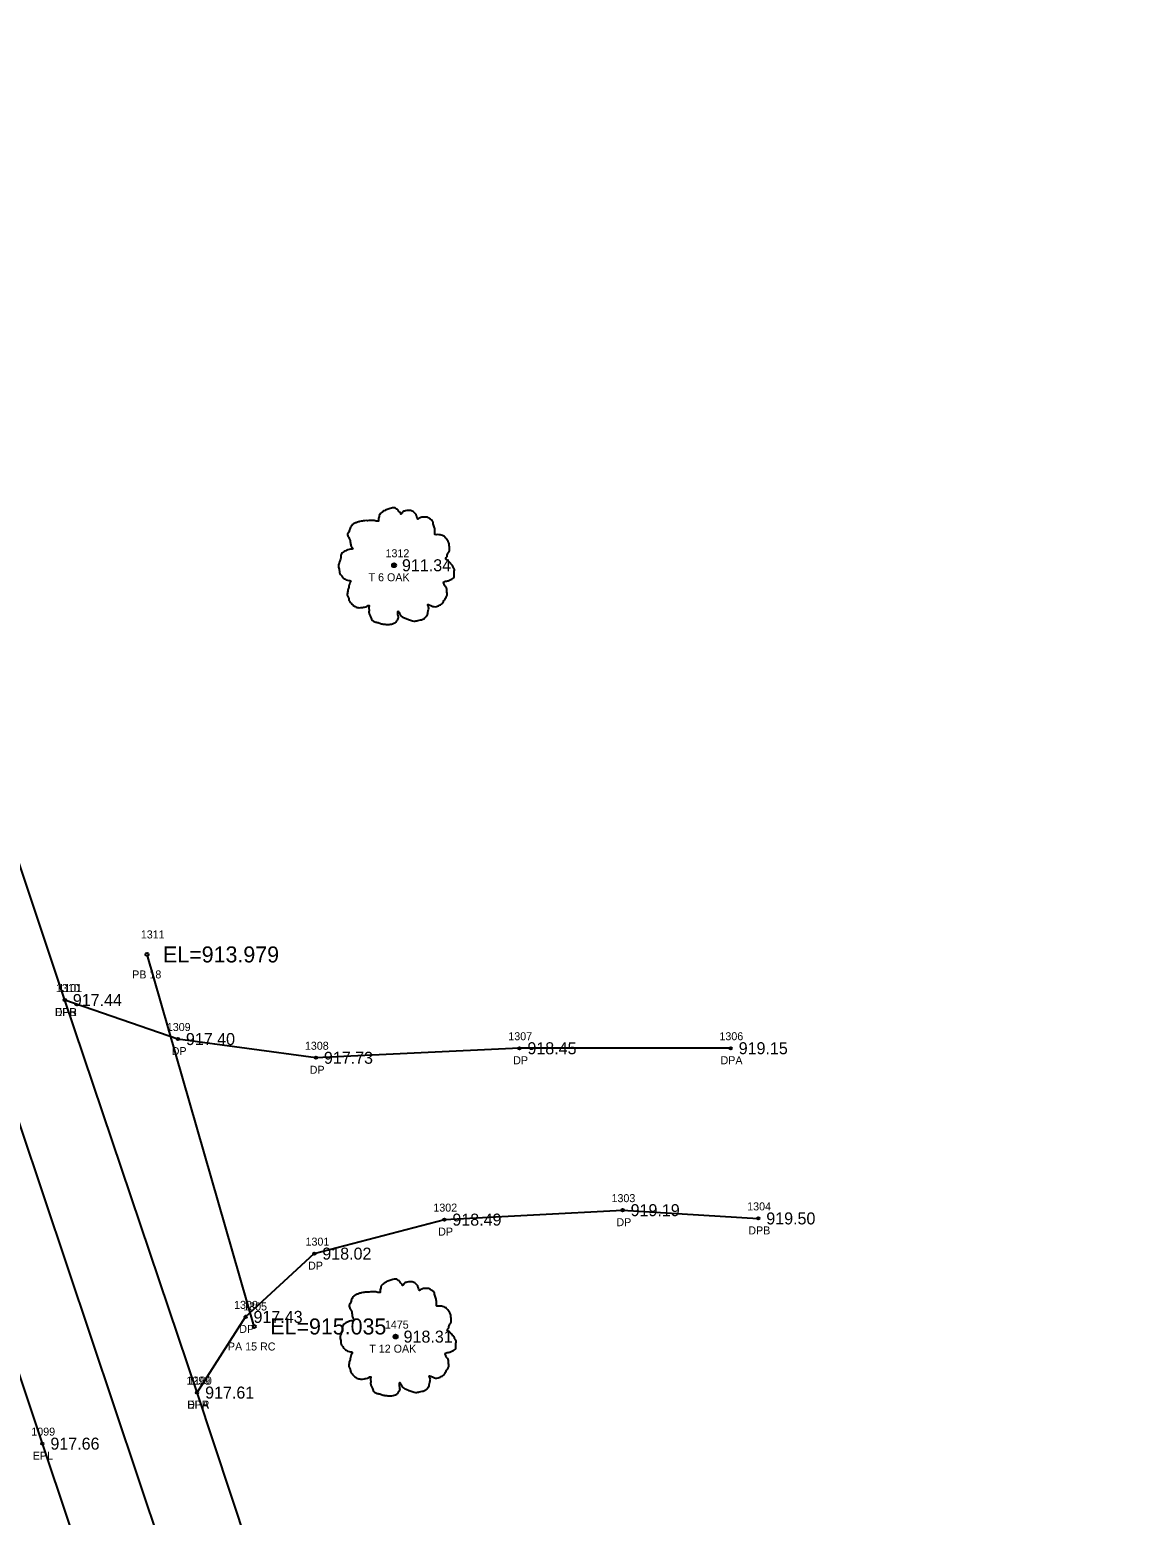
# Model space of a CAD drawing. Extents: x 1528109 to 1531398, y 1157799 to 1162548.
# Drawn here: x 1529835.3 to 1529973.9, y 1159675.3 to 1159860.9 of the extents above; entities that cross this region are included whole.
import ezdxf

# ---------------------------------------------------------------- set-up
doc = ezdxf.new("R2010")
doc.units = 0
for name, color, linetype in [('RD_EX_DR_Pipe', 7, 'Continuous'), ('RD_EX_DR_Pipe_txCode', 7, 'Continuous'), ('RD_EX_Driveway', 7, 'Continuous'), ('RD_EX_Driveway_txCode', 7, 'Continuous'), ('RD_EX_Road', 7, 'Continuous'), ('RD_EX_Road_txCode', 7, 'Continuous'), ('RD_EX_TX_Driveway_ELEV', 7, 'Continuous'), ('RD_EX_TX_Road_ELEV', 7, 'Continuous'), ('RD_EX_TX_VEG_ELEV', 7, 'Continuous'), ('RD_EX_VEG', 7, 'Continuous'), ('RD_EX_VEG_txCode', 7, 'Continuous'), ('RD_HC_Cl', 7, 'Continuous'), ('RD_SMD_Locator', 7, 'Continuous'), ('RD_TX_Pipe_ElevEX', 7, 'Continuous')]:
    doc.layers.add(name, color=color, linetype=linetype)

msp = doc.modelspace()

# ---------------------------------------------------------------- linework, layer by layer
at = {"layer": 'RD_EX_DR_Pipe'}
msp.add_line((1529863.43, 1159698.93), (1529850.02, 1159745.41), dxfattribs=at)
at = {"layer": 'RD_EX_Driveway'}
for points in [[(1529922.98, 1159733.69), (1529896.57, 1159733.69), (1529871.13, 1159732.5), (1529853.88, 1159734.84), (1529839.74, 1159739.71)], [(1529856.28, 1159690.67), (1529862.33, 1159700.13), (1529870.93, 1159708.03), (1529887.19, 1159712.28), (1529909.47, 1159713.46), (1529926.43, 1159712.43)]]:
    msp.add_lwpolyline(points, dxfattribs=at)
at = {"layer": 'RD_EX_Road'}
for points in [[(1530337.52, 1159156.44), (1530294.13, 1159166.93), (1530250.93, 1159177.7), (1530204.42, 1159191.5), (1530168.45, 1159204.97), (1530120.58, 1159231.54), (1530104.56, 1159243.15), (1530086.77, 1159257.61), (1530051.98, 1159290.88), (1530019.2, 1159326.18), (1529978.15, 1159378.31), (1529959.68, 1159408.2), (1529942.81, 1159442.34), (1529934.79, 1159460.88), (1529923.22, 1159491.09), (1529910.46, 1159527.95), (1529895.99, 1159570.93), (1529881.69, 1159613.98), (1529856.28, 1159690.67), (1529839.74, 1159739.71), (1529819.57, 1159800.04), (1529788.95, 1159890.99)], [(1530332.28, 1159136.67), (1530288.96, 1159147.06), (1530245.68, 1159158), (1530197.52, 1159172.18), (1530159.1, 1159186.57), (1530108.6, 1159214.89), (1530072.67, 1159242.37), (1530037.12, 1159276.96), (1530005.21, 1159311.5), (1529961.59, 1159366.88), (1529941.79, 1159398.29), (1529924.06, 1159434.11), (1529903.77, 1159484.39), (1529891.44, 1159520.8), (1529876.79, 1159564.7), (1529862.9, 1159606.82), (1529836.94, 1159684.29), (1529820.66, 1159733.09), (1529800.02, 1159794.4), (1529769.54, 1159884.46)]]:
    msp.add_lwpolyline(points, dxfattribs=at)
at = {"layer": 'RD_EX_VEG'}
for centre, radius in [((1529880.89, 1159794.03), 0.25), ((1529880.88, 1159794.01), 0.0001), ((1529881.09, 1159697.66), 0.25), ((1529881.08, 1159697.64), 0.0001)]:
    msp.add_circle(centre, radius, dxfattribs=at)
for points in [[(1529881.02, 1159801.2), (1529880.72, 1159801.22), (1529880.4, 1159801.12), (1529880.15, 1159801.02), (1529879.92, 1159800.95), (1529879.7, 1159800.85), (1529879.4, 1159800.68), (1529879.17, 1159800.48), (1529879.05, 1159800.23), (1529879, 1159800), (1529878.95, 1159799.73), (1529878.95, 1159799.55), (1529878.82, 1159799.53), (1529878.67, 1159799.55), (1529878.42, 1159799.63), (1529878.17, 1159799.63), (1529877.92, 1159799.63), (1529877.57, 1159799.6), (1529877.22, 1159799.6), (1529876.95, 1159799.55), (1529876.62, 1159799.5), (1529876.25, 1159799.38), (1529875.9, 1159799.25), (1529875.6, 1159799), (1529875.35, 1159798.53), (1529875.23, 1159798.18), (1529875.08, 1159797.93), (1529875.23, 1159797.48), (1529875.4, 1159797.13), (1529875.43, 1159796.93), (1529875.5, 1159796.5), (1529875.6, 1159796.28), (1529875.73, 1159796.08), (1529875.65, 1159796.05), (1529875.28, 1159796), (1529874.98, 1159795.9), (1529874.55, 1159795.68), (1529874.33, 1159795.45), (1529874.23, 1159795.13), (1529874.2, 1159794.78), (1529874.1, 1159794.58), (1529874.03, 1159794.3), (1529874, 1159794.23), (1529873.95, 1159793.9), (1529874.05, 1159793.45), (1529874.08, 1159793.1), (1529874.2, 1159792.88), (1529874.35, 1159792.7), (1529874.53, 1159792.45), (1529874.93, 1159792.23), (1529875.25, 1159792.13), (1529875.45, 1159792.1), (1529875.28, 1159791.6), (1529875.23, 1159791.25), (1529875.1, 1159790.85), (1529875.1, 1159790.78), (1529875.05, 1159790.3), (1529875.2, 1159789.98), (1529875.28, 1159789.6), (1529875.45, 1159789.38), (1529875.73, 1159789.08), (1529876.05, 1159788.86), (1529876.55, 1159788.73), (1529876.95, 1159788.76), (1529877.52, 1159788.93), (1529877.77, 1159789.01), (1529877.75, 1159788.83), (1529877.77, 1159788.46), (1529877.77, 1159788.03), (1529877.92, 1159787.71), (1529878.02, 1159787.43), (1529878.17, 1159787.18), (1529878.5, 1159786.96), (1529878.9, 1159786.88), (1529879.32, 1159786.73), (1529879.77, 1159786.66), (1529880.27, 1159786.63), (1529880.87, 1159786.78), (1529881.15, 1159786.91), (1529881.25, 1159787.08), (1529881.45, 1159787.46), (1529881.4, 1159787.68), (1529881.42, 1159788.28), (1529881.52, 1159788.11), (1529881.7, 1159787.76), (1529882.2, 1159787.46), (1529882.6, 1159787.28), (1529883.07, 1159787.13), (1529883.37, 1159787.06), (1529883.85, 1159787.13), (1529884.22, 1159787.21), (1529884.6, 1159787.33), (1529884.9, 1159787.61), (1529885.07, 1159787.88), (1529885.12, 1159788.16), (1529885.2, 1159788.53), (1529885.25, 1159788.71)], [(1529885.25, 1159788.71), (1529885.17, 1159788.88), (1529885.12, 1159789.13), (1529885.2, 1159789.11), (1529885.37, 1159789.06), (1529885.65, 1159788.93), (1529885.87, 1159788.86), (1529886.2, 1159788.88), (1529886.47, 1159788.98), (1529886.92, 1159789.26), (1529887.2, 1159789.73), (1529887.47, 1159790.13), (1529887.54, 1159790.45), (1529887.49, 1159790.68), (1529887.47, 1159791.18), (1529887.27, 1159791.43), (1529887.22, 1159791.55), (1529887.12, 1159791.95), (1529887.2, 1159792), (1529887.47, 1159792.05), (1529887.84, 1159792.18), (1529888.12, 1159792.3), (1529888.34, 1159792.48), (1529888.42, 1159792.7), (1529888.39, 1159793.1), (1529888.44, 1159793.5), (1529888.37, 1159793.65), (1529888.27, 1159793.8), (1529888.19, 1159794), (1529888.04, 1159794.15), (1529887.94, 1159794.3), (1529887.84, 1159794.4), (1529887.72, 1159794.55), (1529887.54, 1159794.68), (1529887.4, 1159794.73), (1529887.35, 1159794.88), (1529887.49, 1159795.08), (1529887.54, 1159795.18), (1529887.57, 1159795.4), (1529887.79, 1159795.75), (1529887.84, 1159796.15), (1529887.79, 1159796.58), (1529887.74, 1159796.85), (1529887.59, 1159797.13), (1529887.4, 1159797.38), (1529887.27, 1159797.55), (1529887.1, 1159797.68), (1529886.77, 1159797.8), (1529886.52, 1159797.85), (1529886.17, 1159797.85), (1529885.97, 1159797.9), (1529886, 1159797.95), (1529886, 1159798.1), (1529886, 1159798.38), (1529885.92, 1159798.83), (1529885.77, 1159799.33), (1529885.77, 1159799.35), (1529885.67, 1159799.6), (1529885.45, 1159799.8), (1529885.27, 1159799.9), (1529885.07, 1159800.03), (1529884.82, 1159800.05), (1529884.52, 1159800.05), (1529884.25, 1159800), (1529884.05, 1159799.9), (1529883.87, 1159799.78), (1529883.8, 1159799.93), (1529883.7, 1159800.23), (1529883.65, 1159800.38), (1529883.5, 1159800.55), (1529883.27, 1159800.75), (1529882.82, 1159800.87), (1529882.2, 1159800.8), (1529881.9, 1159800.6), (1529881.75, 1159800.43), (1529881.7, 1159800.55), (1529881.5, 1159800.75), (1529881.4, 1159800.92), (1529881.22, 1159801.05), (1529881.07, 1159801.15), (1529880.97, 1159801.2)], [(1529881.23, 1159704.83), (1529880.93, 1159704.85), (1529880.6, 1159704.75), (1529880.35, 1159704.66), (1529880.13, 1159704.58), (1529879.9, 1159704.48), (1529879.6, 1159704.31), (1529879.38, 1159704.11), (1529879.25, 1159703.86), (1529879.2, 1159703.63), (1529879.15, 1159703.36), (1529879.15, 1159703.18), (1529879.03, 1159703.16), (1529878.88, 1159703.18), (1529878.63, 1159703.26), (1529878.38, 1159703.26), (1529878.13, 1159703.26), (1529877.78, 1159703.23), (1529877.43, 1159703.23), (1529877.15, 1159703.18), (1529876.83, 1159703.13), (1529876.45, 1159703.01), (1529876.1, 1159702.88), (1529875.8, 1159702.63), (1529875.55, 1159702.16), (1529875.43, 1159701.81), (1529875.28, 1159701.56), (1529875.43, 1159701.11), (1529875.6, 1159700.76), (1529875.63, 1159700.56), (1529875.7, 1159700.13), (1529875.8, 1159699.91), (1529875.93, 1159699.71), (1529875.85, 1159699.68), (1529875.48, 1159699.63), (1529875.18, 1159699.53), (1529874.75, 1159699.31), (1529874.53, 1159699.08), (1529874.43, 1159698.76), (1529874.4, 1159698.41), (1529874.3, 1159698.21), (1529874.23, 1159697.93), (1529874.2, 1159697.86), (1529874.15, 1159697.53), (1529874.25, 1159697.08), (1529874.28, 1159696.73), (1529874.4, 1159696.51), (1529874.55, 1159696.33), (1529874.73, 1159696.08), (1529875.13, 1159695.86), (1529875.45, 1159695.76), (1529875.65, 1159695.73), (1529875.48, 1159695.23), (1529875.43, 1159694.88), (1529875.3, 1159694.48), (1529875.3, 1159694.41), (1529875.25, 1159693.93), (1529875.4, 1159693.61), (1529875.48, 1159693.24), (1529875.65, 1159693.01), (1529875.93, 1159692.71), (1529876.25, 1159692.49), (1529876.75, 1159692.36), (1529877.15, 1159692.39), (1529877.73, 1159692.56), (1529877.98, 1159692.64), (1529877.95, 1159692.46), (1529877.98, 1159692.09), (1529877.98, 1159691.66), (1529878.13, 1159691.34), (1529878.23, 1159691.06), (1529878.38, 1159690.81), (1529878.7, 1159690.59), (1529879.1, 1159690.51), (1529879.53, 1159690.36), (1529879.98, 1159690.29), (1529880.48, 1159690.26), (1529881.08, 1159690.41), (1529881.35, 1159690.54), (1529881.45, 1159690.71), (1529881.65, 1159691.09), (1529881.6, 1159691.31), (1529881.63, 1159691.91), (1529881.73, 1159691.74), (1529881.9, 1159691.39), (1529882.4, 1159691.09), (1529882.8, 1159690.91), (1529883.28, 1159690.76), (1529883.58, 1159690.69), (1529884.05, 1159690.76), (1529884.42, 1159690.84), (1529884.8, 1159690.96), (1529885.1, 1159691.24), (1529885.27, 1159691.51), (1529885.32, 1159691.79), (1529885.4, 1159692.16), (1529885.45, 1159692.34)], [(1529885.45, 1159692.34), (1529885.37, 1159692.51), (1529885.32, 1159692.76), (1529885.4, 1159692.74), (1529885.57, 1159692.69), (1529885.85, 1159692.56), (1529886.07, 1159692.49), (1529886.4, 1159692.51), (1529886.67, 1159692.61), (1529887.12, 1159692.89), (1529887.4, 1159693.36), (1529887.67, 1159693.76), (1529887.75, 1159694.08), (1529887.7, 1159694.31), (1529887.67, 1159694.81), (1529887.47, 1159695.06), (1529887.42, 1159695.18), (1529887.32, 1159695.58), (1529887.4, 1159695.63), (1529887.67, 1159695.68), (1529888.05, 1159695.81), (1529888.32, 1159695.93), (1529888.55, 1159696.11), (1529888.62, 1159696.33), (1529888.6, 1159696.73), (1529888.65, 1159697.13), (1529888.57, 1159697.28), (1529888.47, 1159697.43), (1529888.4, 1159697.63), (1529888.25, 1159697.78), (1529888.15, 1159697.93), (1529888.05, 1159698.03), (1529887.92, 1159698.18), (1529887.75, 1159698.31), (1529887.6, 1159698.36), (1529887.55, 1159698.51), (1529887.7, 1159698.71), (1529887.75, 1159698.81), (1529887.77, 1159699.03), (1529888, 1159699.38), (1529888.05, 1159699.78), (1529888, 1159700.21), (1529887.95, 1159700.48), (1529887.8, 1159700.76), (1529887.6, 1159701.01), (1529887.47, 1159701.18), (1529887.3, 1159701.31), (1529886.97, 1159701.43), (1529886.72, 1159701.48), (1529886.37, 1159701.48), (1529886.17, 1159701.53), (1529886.2, 1159701.58), (1529886.2, 1159701.73), (1529886.2, 1159702.01), (1529886.12, 1159702.46), (1529885.97, 1159702.96), (1529885.97, 1159702.98), (1529885.87, 1159703.23), (1529885.65, 1159703.43), (1529885.47, 1159703.53), (1529885.27, 1159703.66), (1529885.02, 1159703.68), (1529884.72, 1159703.68), (1529884.45, 1159703.63), (1529884.25, 1159703.53), (1529884.08, 1159703.41), (1529884, 1159703.56), (1529883.9, 1159703.86), (1529883.85, 1159704.01), (1529883.7, 1159704.18), (1529883.48, 1159704.38), (1529883.03, 1159704.51), (1529882.4, 1159704.43), (1529882.1, 1159704.23), (1529881.95, 1159704.06), (1529881.9, 1159704.18), (1529881.7, 1159704.38), (1529881.6, 1159704.56), (1529881.43, 1159704.68), (1529881.28, 1159704.78), (1529881.18, 1159704.83)]]:
    msp.add_spline(points, degree=3, dxfattribs=at)
at = {"layer": 'RD_HC_Cl'}
msp.add_line((1529913.5, 1159487.74), (1529527.85, 1160635.77), dxfattribs=at)
at = {"layer": 'RD_SMD_Locator'}
for centre, radius in [((1529880.89, 1159794.03), 0.15), ((1529850.02, 1159745.41), 0.2), ((1529839.74, 1159739.71), 0.15), ((1529839.74, 1159739.71), 0.15), ((1529853.88, 1159734.84), 0.15), ((1529896.57, 1159733.69), 0.15), ((1529922.98, 1159733.69), 0.15), ((1529871.13, 1159732.5), 0.15), ((1529909.47, 1159713.46), 0.15), ((1529887.19, 1159712.28), 0.15), ((1529926.43, 1159712.43), 0.15), ((1529870.93, 1159708.03), 0.15), ((1529862.33, 1159700.13), 0.15), ((1529863.43, 1159698.93), 0.2), ((1529881.09, 1159697.66), 0.15), ((1529856.28, 1159690.67), 0.15), ((1529856.28, 1159690.67), 0.15), ((1529836.94, 1159684.29), 0.15)]:
    msp.add_circle(centre, radius, dxfattribs=at)

# ---------------------------------------------------------------- texts
at = {"layer": 'RD_EX_DR_Pipe_txCode'}
for s, p in [('1311', (1529849.24, 1159747.41)), ('PB 18', (1529848.16, 1159742.41)), ('1305', (1529862.04, 1159700.93)), ('PA 15 RC', (1529860.13, 1159695.93))]:
    msp.add_text(s, height=1, dxfattribs=at).set_placement(p)
at = {"layer": 'RD_EX_Driveway_txCode'}
for s, p in [('1310', (1529838.63, 1159740.71)), ('DPB', (1529838.48, 1159737.71)), ('1309', (1529852.49, 1159735.84)), ('1307', (1529895.18, 1159734.69)), ('1306', (1529921.57, 1159734.69)), ('DP', (1529853.1, 1159732.84)), ('1308', (1529869.75, 1159733.5)), ('DP', (1529870.35, 1159730.5)), ('DP', (1529895.79, 1159731.69)), ('DPA', (1529921.71, 1159731.69)), ('1303', (1529908.08, 1159714.46)), ('1302', (1529885.81, 1159713.28)), ('1304', (1529925.04, 1159713.43)), ('DP', (1529886.41, 1159710.28)), ('DP', (1529908.69, 1159711.46)), ('DPB', (1529925.18, 1159710.43)), ('1301', (1529869.83, 1159709.03)), ('DP', (1529870.15, 1159706.03)), ('1300', (1529860.9, 1159701.13)), ('DP', (1529861.55, 1159698.13)), ('1299', (1529854.94, 1159691.67)), ('DPA', (1529855.02, 1159688.67))]:
    msp.add_text(s, height=1, dxfattribs=at).set_placement(p)
at = {"layer": 'RD_EX_Road_txCode'}
for s, p in [('1101', (1529838.92, 1159740.71)), ('EPR', (1529838.51, 1159737.71)), ('1100', (1529855.14, 1159691.67)), ('EPR', (1529855.06, 1159688.67)), ('1099', (1529835.55, 1159685.29)), ('EPL', (1529835.73, 1159682.29))]:
    msp.add_text(s, height=1, dxfattribs=at).set_placement(p)
at = {"layer": 'RD_EX_TX_Driveway_ELEV'}
for s, p in [('917.44', (1529840.74, 1159738.96)), ('917.40', (1529854.88, 1159734.09)), ('917.73', (1529872.13, 1159731.75)), ('918.45', (1529897.57, 1159732.94)), ('919.15', (1529923.98, 1159732.94)), ('918.49', (1529888.19, 1159711.53)), ('919.19', (1529910.47, 1159712.71)), ('919.50', (1529927.43, 1159711.68)), ('918.02', (1529871.93, 1159707.28)), ('917.43', (1529863.33, 1159699.38)), ('917.61', (1529857.28, 1159689.92))]:
    msp.add_text(s, height=1.5, dxfattribs=at).set_placement(p)
at = {"layer": 'RD_EX_TX_Road_ELEV'}
for s, p in [('917.44', (1529840.74, 1159738.96)), ('917.61', (1529857.28, 1159689.92)), ('917.66', (1529837.94, 1159683.54))]:
    msp.add_text(s, height=1.5, dxfattribs=at).set_placement(p)
at = {"layer": 'RD_EX_TX_VEG_ELEV'}
for s, p in [('911.34', (1529881.89, 1159793.28)), ('918.31', (1529882.09, 1159696.91))]:
    msp.add_text(s, height=1.5, dxfattribs=at).set_placement(p)
at = {"layer": 'RD_EX_VEG_txCode'}
for s, p in [('1312', (1529879.83, 1159795.03)), ('T 6 OAK', (1529877.71, 1159792.03)), ('1475', (1529879.75, 1159698.66)), ('T 12 OAK', (1529877.8, 1159695.66))]:
    msp.add_text(s, height=1, dxfattribs=at).set_placement(p)
at = {"layer": 'RD_TX_Pipe_ElevEX'}
for s, p in [('EL=913.979', (1529852.02, 1159744.41)), ('EL=915.035', (1529865.43, 1159697.93))]:
    msp.add_text(s, height=2, dxfattribs=at).set_placement(p)

doc.saveas('drawing.dxf')
